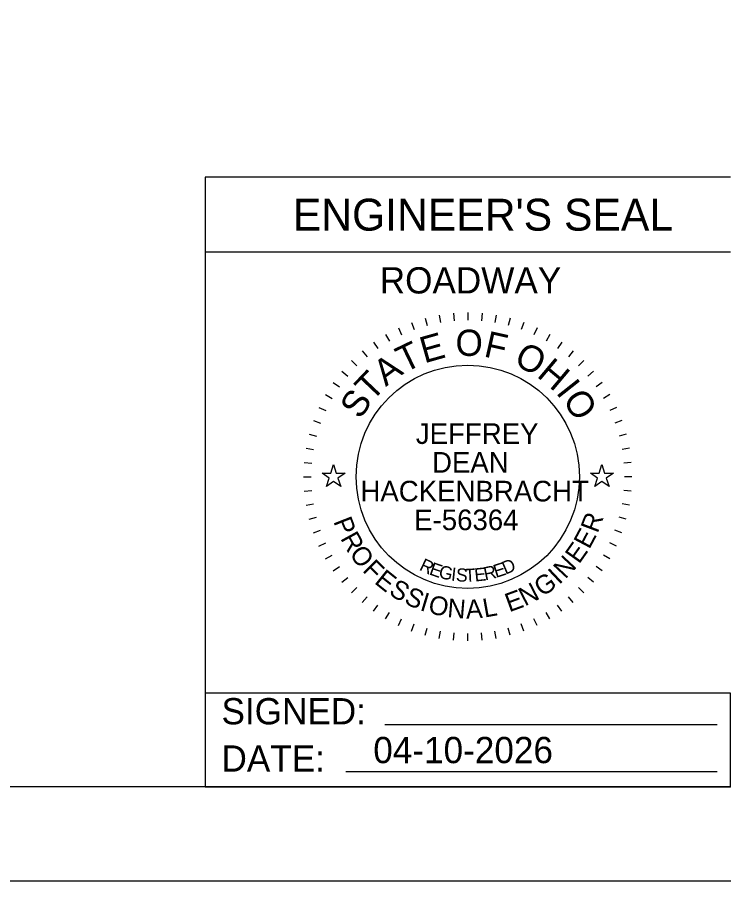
# Model space of a CAD drawing. Extents: x 0 to 45.4, y -2.2 to 22.
# Drawn here: x 7.449 to 11.214, y 0 to 4.602 of the extents above; entities that cross this region are included whole.
import ezdxf

# ---------------------------------------------------------------- set-up
doc = ezdxf.new("R2010")
doc.units = 0
for name, color, linetype in [('Default', 7, 'Continuous'), ('SH_Border', 7, 'Continuous'), ('SH_Cut_Line', 7, 'Continuous'), ('SH_Data', 7, 'Continuous'), ('SH_Text', 7, 'Continuous')]:
    doc.layers.add(name, color=color, linetype=linetype)

msp = doc.modelspace()

# ---------------------------------------------------------------- linework, layer by layer
at = {"layer": 'Default'}
for points in [[(9.0736, 2.1732), (9.1205, 2.1732), (9.135, 2.2178), (9.1495, 2.1732), (9.1964, 2.1732), (9.1585, 2.1456), (9.173, 2.1011), (9.135, 2.1286), (9.097, 2.1011), (9.1115, 2.1456)], [(10.5036, 2.1732), (10.5505, 2.1732), (10.565, 2.2178), (10.5795, 2.1732), (10.6264, 2.1732), (10.5885, 2.1456), (10.603, 2.1011), (10.565, 2.1286), (10.527, 2.1011), (10.5415, 2.1456)]]:
    msp.add_lwpolyline(points, close=True, dxfattribs=at)
at = {"layer": 'SH_Border'}
msp.add_lwpolyline([(1.5, 21.5), (33.5, 21.5), (33.5, 0.5), (1.5, 0.5)], close=True, dxfattribs=at)
at = {"layer": 'SH_Cut_Line'}
msp.add_lwpolyline([(0, 0), (34, 0), (34, 22), (0, 22)], close=True, dxfattribs=at)
at = {"layer": 'SH_Data'}
for p, q in [((11.25, 3.75), (8.45, 3.75)), ((8.45, 3.75), (8.45, 0.5)), ((11.25, 3.35), (8.45, 3.35)), ((9.6235, 2.9985), (9.6339, 2.9598)), ((9.6981, 3.015), (9.705, 2.9756)), ((9.7737, 3.0249), (9.7772, 2.9851)), ((9.85, 3.0283), (9.85, 2.9883)), ((9.9263, 3.0249), (9.9228, 2.9851)), ((10.0019, 3.015), (9.995, 2.9756)), ((10.0765, 2.9985), (10.0661, 2.9598)), ((9.4802, 2.9463), (9.4971, 2.91)), ((9.5507, 2.9755), (9.5644, 2.9379)), ((10.1493, 2.9755), (10.1356, 2.9379)), ((10.2198, 2.9463), (10.2029, 2.91)), ((9.4125, 2.911), (9.4325, 2.8764)), ((10.2875, 2.911), (10.2675, 2.8764)), ((9.3481, 2.87), (9.3711, 2.8373)), ((10.3519, 2.87), (10.3289, 2.8373)), ((9.2876, 2.8236), (9.3133, 2.7929)), ((10.4124, 2.8236), (10.3867, 2.7929)), ((9.2313, 2.772), (9.2596, 2.7437)), ((10.4687, 2.772), (10.4404, 2.7437)), ((9.1797, 2.7157), (9.2104, 2.69)), ((10.5203, 2.7157), (10.4896, 2.69)), ((9.1332, 2.6552), (9.166, 2.6322)), ((10.5668, 2.6552), (10.534, 2.6322)), ((9.0922, 2.5908), (9.1269, 2.5708)), ((10.6078, 2.5908), (10.5731, 2.5708)), ((9.057, 2.5231), (9.0932, 2.5062)), ((10.643, 2.5231), (10.6068, 2.5062)), ((9.0278, 2.4525), (9.0654, 2.4389)), ((10.6722, 2.4525), (10.6346, 2.4389)), ((9.0048, 2.3797), (9.0435, 2.3694)), ((10.6952, 2.3797), (10.6565, 2.3694)), ((8.9883, 2.3052), (9.0277, 2.2983)), ((10.7117, 2.3052), (10.6723, 2.2983)), ((8.9783, 2.2295), (9.0182, 2.2261)), ((10.7217, 2.2295), (10.6818, 2.2261)), ((8.975, 2.1533), (9.015, 2.1533)), ((10.725, 2.1533), (10.685, 2.1533)), ((8.9783, 2.077), (9.0182, 2.0805)), ((10.7217, 2.077), (10.6818, 2.0805)), ((8.9883, 2.0013), (9.0277, 2.0083)), ((10.7117, 2.0013), (10.6723, 2.0083)), ((9.0048, 1.9268), (9.0435, 1.9372)), ((10.6952, 1.9268), (10.6565, 1.9372)), ((9.0278, 1.854), (9.0654, 1.8677)), ((10.6722, 1.854), (10.6346, 1.8677)), ((9.057, 1.7835), (9.0932, 1.8004)), ((10.643, 1.7835), (10.6068, 1.8004)), ((9.0922, 1.7158), (9.1269, 1.7358)), ((10.6078, 1.7158), (10.5731, 1.7358)), ((9.1332, 1.6514), (9.166, 1.6743)), ((10.5668, 1.6514), (10.534, 1.6743)), ((9.1797, 1.5908), (9.2104, 1.6165)), ((10.5203, 1.5908), (10.4896, 1.6165)), ((9.2313, 1.5346), (9.2596, 1.5628)), ((10.4687, 1.5346), (10.4404, 1.5628)), ((9.2876, 1.483), (9.3133, 1.5136)), ((10.4124, 1.483), (10.3867, 1.5136)), ((9.3481, 1.4365), (9.3711, 1.4693)), ((9.4125, 1.3955), (9.4325, 1.4301)), ((10.2875, 1.3955), (10.2675, 1.4301)), ((10.3519, 1.4365), (10.3289, 1.4693)), ((9.4802, 1.3603), (9.4971, 1.3965)), ((10.2198, 1.3603), (10.2029, 1.3965)), ((9.5507, 1.331), (9.5644, 1.3686)), ((9.6235, 1.3081), (9.6339, 1.3467)), ((10.0765, 1.3081), (10.0661, 1.3467)), ((10.1493, 1.331), (10.1356, 1.3686)), ((9.6981, 1.2916), (9.705, 1.331)), ((9.7737, 1.2816), (9.7772, 1.3215)), ((9.85, 1.2783), (9.85, 1.3183)), ((9.9263, 1.2816), (9.9228, 1.3215)), ((10.0019, 1.2916), (9.995, 1.331)), ((11.25, 0.5), (8.45, 0.5))]:
    msp.add_line(p, q, dxfattribs=at)
msp.add_lwpolyline([(11.25, 0.5), (11.25, 1), (8.45, 1), (8.45, 0.5)], close=True, dxfattribs=at)
msp.add_circle((9.85, 2.1533), 0.595, dxfattribs=at)
at = {"layer": 'SH_Text'}
for p, q in [((9.4087, 0.8335), (11.1789, 0.8335)), ((9.201, 0.5815), (11.1789, 0.5815))]:
    msp.add_line(p, q, dxfattribs=at)

# ---------------------------------------------------------------- texts
at = {"layer": 'SH_Data'}
for s, height, p in [("ENGINEER'S SEAL", 0.17, (8.9176, 3.465)), ('ROADWAY', 0.14, (9.3811, 3.13)), ('JEFFREY', 0.11, (9.5733, 2.3282)), ('DEAN', 0.11, (9.6597, 2.1749)), ('HACKENBRACHT', 0.11, (9.278, 2.0216)), ('E-56364', 0.11, (9.5645, 1.8684))]:
    msp.add_text(s, height=height, dxfattribs=at).set_placement(p)
for s, height, rotation, p in [('E', 0.14, 15.7571, (9.6184, 2.7571)), ('O', 0.14, 359.7812, (9.7847, 2.7975)), ('F', 0.14, 347.4362, (9.9311, 2.795)), ('T', 0.14, 25.7167, (9.5116, 2.7051)), ('O', 0.14, 332.2586, (10.0898, 2.7548)), ('A', 0.14, 36.4747, (9.4134, 2.6314)), ('H', 0.14, 319.9136, (10.2132, 2.6894)), ('T', 0.14, 46.4344, (9.3383, 2.5497)), ('I', 0.14, 308.367, (10.3165, 2.6016)), ('S', 0.14, 57.1924, (9.2781, 2.4547)), ('O', 0.14, 303.1491, (10.3521, 2.5621)), ('P', 0.1, 291.494, (9.1323, 1.9153)), ('R', 0.1, 69.2322, (10.5419, 1.8486)), ('R', 0.1, 298.7311, (9.169, 1.825)), ('E', 0.1, 61.9951, (10.4976, 1.7631)), ('E', 0.1, 54.758, (10.4433, 1.6846)), ('O', 0.1, 306.4666, (9.2155, 1.7416)), ('F', 0.1, 314.7068, (9.2843, 1.6516)), ('R', 0.07, 334.487, (9.5875, 1.6583)), ('D', 0.07, 23.3052, (10.051, 1.6303)), ('N', 0.1, 47.0224, (10.3702, 1.6041)), ('E', 0.1, 321.4393, (9.3478, 1.5881)), ('E', 0.07, 341.04, (9.6406, 1.6333)), ('G', 0.07, 347.4752, (9.6914, 1.6151)), ('I', 0.07, 353.7858, (9.7591, 1.6001)), ('S', 0.07, 356.8926, (9.7858, 1.5962)), ('T', 0.07, 3.0061, (9.8357, 1.592)), ('E', 0.07, 6.0117, (9.8889, 1.5945)), ('R', 0.07, 11.9184, (9.9425, 1.6007)), ('E', 0.07, 17.6836, (9.9998, 1.6135)), ('I', 0.1, 43.287, (10.3368, 1.5747)), ('G', 0.1, 35.0469, (10.2481, 1.5103)), ('S', 0.1, 328.6764, (9.4243, 1.5285)), ('N', 0.1, 27.3113, (10.1545, 1.4608)), ('S', 0.1, 335.9134, (9.5064, 1.4799)), ('I', 0.1, 343.1505, (9.5906, 1.443)), ('O', 0.1, 346.8859, (9.6339, 1.4284)), ('E', 0.1, 20.0742, (10.0712, 1.4303)), ('N', 0.1, 355.1261, (9.7388, 1.405)), ('A', 0.1, 2.8617, (9.8423, 1.3969)), ('L', 0.1, 10.0987, (9.9394, 1.4023))]:
    msp.add_text(s, height=height, rotation=rotation, dxfattribs=at).set_placement(p)
at = {"layer": 'SH_Text'}
for s, p in [('SIGNED:', (8.5376, 0.8335)), ('04-10-2026', (9.3466, 0.6266)), ('DATE:', (8.5376, 0.5815))]:
    msp.add_text(s, height=0.14, dxfattribs=at).set_placement(p)

doc.saveas('drawing.dxf')
